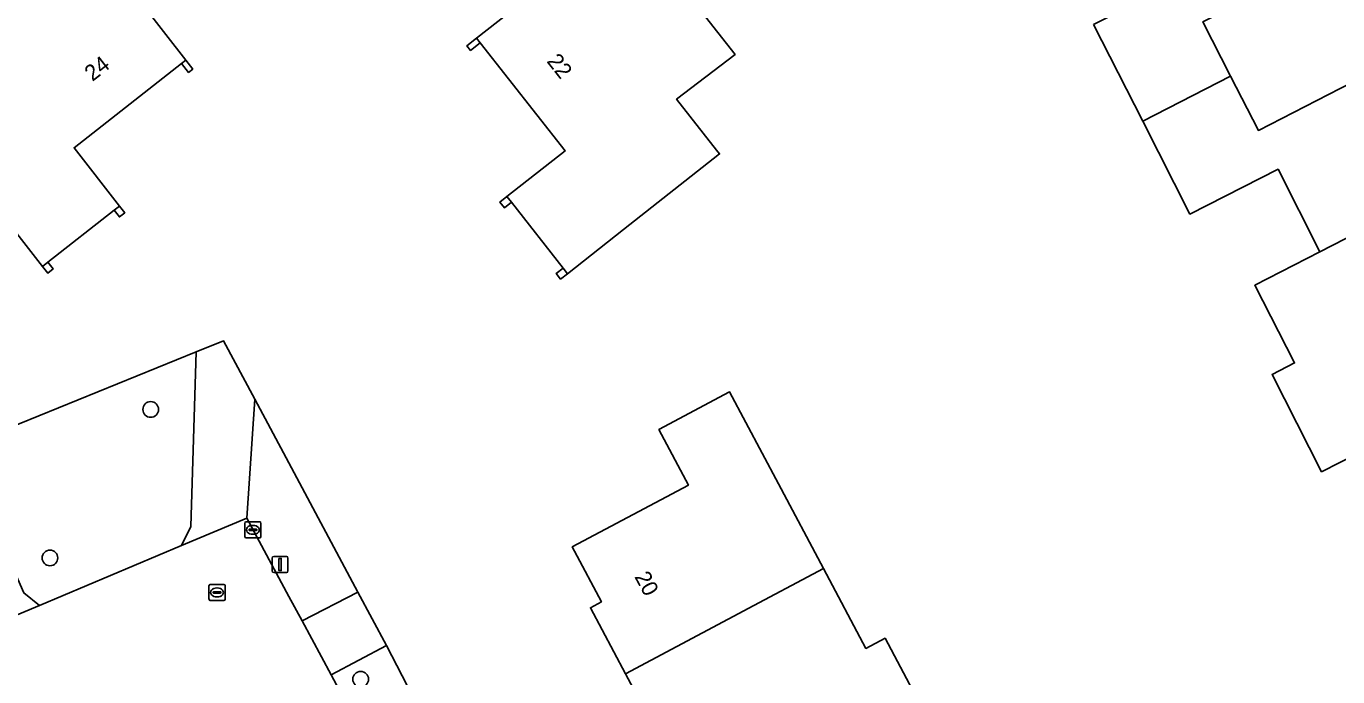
# Model space of a CAD drawing. Extents: x 162417 to 163722, y 384268 to 385417.
# Drawn here: x 163483.6 to 163565.5, y 384925 to 384965.6 of the extents above; entities that cross this region are included whole.
import ezdxf

# ---------------------------------------------------------------- set-up
doc = ezdxf.new("R2010")
doc.units = 0
for name, color, linetype in [('IMGEO_Boom', 7, 'Continuous'), ('IMGEO_Erf', 7, 'Continuous'), ('IMGEO_Groenvoorziening', 7, 'Continuous'), ('IMGEO_Kolk', 7, 'Continuous'), ('IMGEO_Lichtmast', 7, 'Continuous'), ('IMGEO_Muur', 7, 'Continuous'), ('IMGEO_Pand', 7, 'Continuous'), ('IMGEO_Pand_nummerreeks', 7, 'Continuous'), ('IMGEO_Rijbaan_lokaal_gesloten', 7, 'Continuous'), ('IMGEO_Rioolput', 7, 'Continuous'), ('IMGEO_Voetpad_open', 7, 'Continuous')]:
    doc.layers.add(name, color=color, linetype=linetype)

msp = doc.modelspace()

# ---------------------------------------------------------------- linework, layer by layer
at = {"layer": 'IMGEO_Boom'}
for centre in [(163491.37, 384941.649), (163485.084, 384932.387), (163504.475, 384924.82)]:
    msp.add_circle(centre, 0.489, dxfattribs=at)
at = {"layer": 'IMGEO_Erf'}
msp.add_lwpolyline([(163517.384, 384950.12), (163516.948, 384949.777), (163516.672, 384950.127), (163517.108, 384950.471), (163513.88, 384954.573), (163513.444, 384954.23), (163513.166, 384954.583), (163513.602, 384954.926), (163517.23, 384957.781), (163511.929, 384964.517), (163511.333, 384964.048), (163511.104, 384964.339), (163511.7, 384964.808), (163515.034, 384967.432), (163517.566, 384969.425), (163518.37, 384968.403), (163521.985, 384971.248), (163527.844, 384963.8), (163524.188, 384961.001), (163526.689, 384957.823), (163526.874, 384957.588), (163520.878, 384952.87)], close=True, dxfattribs=at)
for points in [[(163490.912, 384966.818), (163493.56, 384963.439), (163493.996, 384962.883), (163493.734, 384962.677), (163493.298, 384963.233), (163486.585, 384957.972), (163489.43, 384954.341), (163489.756, 384953.925), (163489.419, 384953.662), (163489.094, 384954.077), (163484.955, 384950.834), (163485.281, 384950.419), (163484.944, 384950.154), (163484.618, 384950.57), (163481.829, 384954.129), (163479.862, 384952.587), (163476.911, 384952.94), (163474.138, 384956.462), (163474.608, 384960.569), (163476.576, 384960.345), (163476.793, 384960.516), (163477.154, 384960.055), (163480.497, 384962.675), (163480.747, 384965.663)], [(163566.719, 384938.915), (163564.445, 384937.758), (163561.353, 384943.836), (163562.758, 384944.551), (163560.274, 384949.399), (163564.346, 384951.484), (163561.728, 384956.63), (163556.229, 384953.832), (163553.281, 384959.628), (163550.211, 384965.663)], [(163557.032, 384965.826), (163558.766, 384962.44), (163560.499, 384959.055), (163567.785, 384962.786)], [(163479.466, 384939.261), (163494.207, 384945.241), (163495.918, 384945.927), (163497.872, 384942.291), (163500, 384938.325), (163504.307, 384930.256), (163506.079, 384926.915), (163514.598, 384910.454), (163515.734, 384908.25), (163515.928, 384908.35), (163518.056, 384909.494), (163552.107, 384845.87), (163579.211, 384794.807)], [(163523.203, 384921.016), (163521.007, 384925.15), (163518.811, 384929.284), (163519.5, 384929.65), (163517.818, 384932.817), (163517.68, 384933.078), (163524.927, 384936.928), (163523.084, 384940.398), (163527.5, 384942.745), (163530.551, 384937.002), (163533.357, 384931.72), (163536.002, 384926.739), (163537.203, 384927.376), (163540.273, 384921.598)]]:
    msp.add_lwpolyline(points, dxfattribs=at)
at = {"layer": 'IMGEO_Groenvoorziening'}
for points in [[(163493.3, 384933.155), (163493.875, 384934.348), (163494.207, 384945.241), (163479.466, 384939.261), (163483.455, 384930.207), (163484.425, 384929.423)], [(163500, 384938.325), (163497.872, 384942.291), (163497.361, 384934.859), (163500, 384929.981), (163500.82, 384928.465), (163504.307, 384930.256)], [(163506.079, 384926.915), (163502.633, 384925.084), (163503.817, 384922.872), (163505.981, 384923.979), (163513.523, 384909.9), (163514.598, 384910.454)]]:
    msp.add_lwpolyline(points, close=True, dxfattribs=at)
at = {"layer": 'IMGEO_Kolk'}
for p, q in [((163497.248, 384933.714), (163497.248, 384934.566)), ((163497.323, 384934.64), (163498.175, 384934.64)), ((163497.736, 384934.42), (163497.761, 384934.42)), ((163498.249, 384934.566), (163498.249, 384933.714)), ((163498.175, 384933.64), (163497.323, 384933.64)), ((163497.507, 384934.134), (163497.507, 384934.146)), ((163497.945, 384934.097), (163497.547, 384934.097)), ((163497.55, 384934.183), (163497.948, 384934.183)), ((163497.759, 384933.86), (163497.734, 384933.86)), ((163497.991, 384934.146), (163497.991, 384934.134))]:
    msp.add_line(p, q, dxfattribs=at)
for points in [[(163497.248, 384933.714), (163497.248, 384934.566)], [(163497.323, 384934.64), (163498.175, 384934.64)], [(163498.249, 384934.566), (163498.249, 384933.714)], [(163498.175, 384933.64), (163497.323, 384933.64)]]:
    msp.add_lwpolyline(points, dxfattribs=at)
for centre, radius, start, end in [((163497.325, 384934.564), 0.0765, 91.55205, 178.44795), ((163497.325, 384934.564), 0.0765, 91.55205, 178.44795), ((163498.173, 384934.564), 0.0765, 1.55205, 88.44795), ((163498.173, 384934.564), 0.0765, 1.55205, 88.44795), ((163497.325, 384933.716), 0.0765, 181.55205, 268.44795), ((163497.325, 384933.716), 0.0765, 181.55205, 268.44795), ((163497.547, 384934.143), 0.0403, 85.87752, 175.75265), ((163497.544, 384934.133), 0.0366, 178.93798, 274.71019), ((163497.948, 384934.14), 0.043, 264.86636, 352.45326), ((163497.952, 384934.145), 0.0386, 1.73085, 96.63898), ((163498.173, 384933.716), 0.0765, 271.55205, 358.44795), ((163498.173, 384933.716), 0.0765, 271.55205, 358.44795)]:
    msp.add_arc(centre, radius, start, end, dxfattribs=at)
for centre, major_axis, ratio, start_param, end_param in [((163497.735, 384934.14), (-0.387, 0.002), 0.722429, 4.712389, 7.853982), ((163497.76, 384934.14), (-0.39, 0.002), 0.717154, 1.570796, 4.712389)]:
    msp.add_ellipse(centre, major_axis=major_axis, ratio=ratio, start_param=start_param, end_param=end_param, dxfattribs=at)
at = {"layer": 'IMGEO_Lichtmast'}
for p, q in [((163498.949, 384931.577), (163498.949, 384932.377)), ((163498.949, 384932.377), (163498.949, 384931.577)), ((163499.049, 384932.477), (163499.839, 384932.477)), ((163499.839, 384932.477), (163499.049, 384932.477)), ((163499.939, 384932.377), (163499.939, 384931.577)), ((163499.939, 384931.577), (163499.939, 384932.377)), ((163499.839, 384931.477), (163499.049, 384931.477)), ((163499.049, 384931.477), (163499.839, 384931.477))]:
    msp.add_line(p, q, dxfattribs=at)
msp.add_lwpolyline([(163499.369, 384932.352), (163499.519, 384932.352), (163499.519, 384931.602), (163499.369, 384931.602), (163499.369, 384932.352)], dxfattribs=at)
for centre, start, end in [((163499.049, 384932.377), 90, 180), ((163499.049, 384932.377), 90, 180), ((163499.839, 384932.377), 0, 90), ((163499.839, 384932.377), 360, 90), ((163499.049, 384931.577), 180, 270), ((163499.049, 384931.577), 180, 270), ((163499.839, 384931.577), 270, 0), ((163499.839, 384931.577), 270, 0)]:
    msp.add_arc(centre, 0.1, start, end, dxfattribs=at)
at = {"layer": 'IMGEO_Muur'}
for points in [[(163511.929, 384964.517), (163511.7, 384964.808), (163511.104, 384964.339), (163511.333, 384964.048)], [(163493.56, 384963.439), (163493.298, 384963.233), (163493.734, 384962.677), (163493.996, 384962.883)], [(163513.602, 384954.926), (163513.166, 384954.583), (163513.444, 384954.23), (163513.88, 384954.573)], [(163489.756, 384953.925), (163489.43, 384954.341), (163489.094, 384954.077), (163489.419, 384953.662)], [(163484.955, 384950.834), (163484.618, 384950.57), (163484.944, 384950.154), (163485.281, 384950.419)], [(163517.108, 384950.471), (163516.672, 384950.127), (163516.948, 384949.777), (163517.384, 384950.12)]]:
    msp.add_lwpolyline(points, close=True, dxfattribs=at)
at = {"layer": 'IMGEO_Pand'}
for points in [[(163550.211, 384965.663), (163553.281, 384959.628), (163558.766, 384962.44), (163557.032, 384965.826), (163564.327, 384969.562), (163564.17, 384969.868), (163562.49, 384973.148), (163563.242, 384973.533), (163561.148, 384977.622), (163549.382, 384971.771), (163552.021, 384966.584)], [(163524.188, 384961.001), (163527.844, 384963.8), (163521.985, 384971.248), (163518.37, 384968.403), (163517.566, 384969.425), (163515.034, 384967.432), (163511.7, 384964.808), (163511.929, 384964.517), (163517.23, 384957.781), (163513.602, 384954.926), (163513.88, 384954.573), (163517.108, 384950.471), (163517.384, 384950.12), (163520.878, 384952.87), (163526.874, 384957.588), (163526.689, 384957.823)], [(163476.911, 384952.94), (163479.862, 384952.587), (163481.829, 384954.129), (163484.618, 384950.57), (163484.955, 384950.834), (163489.094, 384954.077), (163489.43, 384954.341), (163486.585, 384957.972), (163493.298, 384963.233), (163493.56, 384963.439), (163490.912, 384966.818), (163488.949, 384969.324), (163486.84, 384967.671), (163485.497, 384969.386), (163481.736, 384966.438), (163480.747, 384965.663), (163480.497, 384962.675), (163477.154, 384960.055), (163476.793, 384960.516), (163476.576, 384960.345), (163474.608, 384960.569), (163474.138, 384956.462)], [(163553.281, 384959.628), (163556.229, 384953.832), (163561.728, 384956.63), (163564.346, 384951.484), (163572.333, 384955.575), (163570.232, 384959.678), (163569.554, 384959.331), (163567.914, 384962.534), (163567.785, 384962.786), (163560.499, 384959.055), (163558.766, 384962.44)], [(163561.353, 384943.836), (163564.445, 384937.758), (163566.719, 384938.915), (163566.822, 384938.713), (163570.017, 384940.348), (163569.886, 384940.604), (163568.2, 384943.896), (163573.613, 384946.667), (163575.47, 384947.618), (163575.298, 384947.953), (163573.691, 384951.09), (163574.435, 384951.47), (163572.333, 384955.575), (163564.346, 384951.484), (163560.274, 384949.399), (163562.758, 384944.551)], [(163527.5, 384942.745), (163523.084, 384940.398), (163524.927, 384936.928), (163517.68, 384933.078), (163517.818, 384932.817), (163519.5, 384929.65), (163518.811, 384929.284), (163521.007, 384925.15), (163529.011, 384929.411), (163532.695, 384931.368), (163533.357, 384931.72), (163530.551, 384937.002)], [(163537.203, 384927.376), (163536.002, 384926.739), (163533.357, 384931.72), (163532.695, 384931.368), (163529.011, 384929.411), (163521.007, 384925.15), (163523.203, 384921.016), (163523.973, 384921.425), (163525.67, 384918.229), (163525.807, 384917.971), (163527.599, 384918.924), (163533.076, 384921.834), (163534.758, 384918.668), (163537.142, 384919.935), (163540.273, 384921.598)]]:
    msp.add_lwpolyline(points, close=True, dxfattribs=at)
at = {"layer": 'IMGEO_Rijbaan_lokaal_gesloten'}
msp.add_lwpolyline([(163496.246, 384922.739), (163497.491, 384920.419), (163503.817, 384922.872), (163502.633, 384925.084), (163500.82, 384928.465), (163500, 384929.981), (163497.361, 384934.859), (163493.3, 384933.155), (163484.425, 384929.423), (163480.987, 384927.976), (163480.777, 384927.888), (163459.676, 384919.014), (163456.078, 384917.501), (163455.799, 384917.384), (163407.071, 384896.895)], dxfattribs=at)
at = {"layer": 'IMGEO_Rioolput'}
for p, q in [((163495.009, 384929.806), (163495.009, 384930.658)), ((163495.084, 384930.732), (163495.936, 384930.732)), ((163495.268, 384930.226), (163495.268, 384930.238)), ((163495.311, 384930.275), (163495.709, 384930.275)), ((163495.497, 384930.512), (163495.522, 384930.512)), ((163495.752, 384930.238), (163495.752, 384930.226)), ((163496.01, 384930.658), (163496.01, 384929.806)), ((163495.936, 384929.732), (163495.084, 384929.732)), ((163495.706, 384930.189), (163495.308, 384930.189)), ((163495.52, 384929.952), (163495.495, 384929.952))]:
    msp.add_line(p, q, dxfattribs=at)
for points in [[(163495.009, 384929.806), (163495.009, 384930.658)], [(163495.084, 384930.732), (163495.936, 384930.732)], [(163496.01, 384930.658), (163496.01, 384929.806)], [(163495.936, 384929.732), (163495.084, 384929.732)]]:
    msp.add_lwpolyline(points, dxfattribs=at)
for centre, radius, start, end in [((163495.086, 384930.656), 0.0765, 91.55205, 178.44795), ((163495.086, 384930.656), 0.0765, 91.55205, 178.44795), ((163495.308, 384930.235), 0.0403, 85.87752, 175.75265), ((163495.305, 384930.225), 0.0366, 178.93798, 274.71019), ((163495.709, 384930.232), 0.043, 264.86636, 352.45326), ((163495.713, 384930.237), 0.0386, 1.73085, 96.63898), ((163495.934, 384930.656), 0.0765, 1.55205, 88.44795), ((163495.934, 384930.656), 0.0765, 1.55205, 88.44795), ((163495.086, 384929.808), 0.0765, 181.55205, 268.44795), ((163495.086, 384929.808), 0.0765, 181.55205, 268.44795), ((163495.934, 384929.808), 0.0765, 271.55205, 358.44795), ((163495.934, 384929.808), 0.0765, 271.55205, 358.44795)]:
    msp.add_arc(centre, radius, start, end, dxfattribs=at)
for centre, major_axis, ratio, start_param, end_param in [((163495.496, 384930.232), (-0.387, 0.002), 0.722429, 4.712389, 7.853982), ((163495.521, 384930.232), (-0.39, 0.002), 0.717154, 1.570796, 4.712389)]:
    msp.add_ellipse(centre, major_axis=major_axis, ratio=ratio, start_param=start_param, end_param=end_param, dxfattribs=at)
at = {"layer": 'IMGEO_Voetpad_open'}
for points in [[(163493.3, 384933.155), (163497.361, 384934.859), (163497.872, 384942.291), (163495.918, 384945.927), (163494.207, 384945.241), (163493.875, 384934.348)], [(163479.466, 384939.261), (163477.129, 384938.273), (163476.005, 384937.8), (163478.195, 384934.989), (163480.791, 384929.164), (163480.777, 384927.888), (163480.987, 384927.976), (163484.425, 384929.423), (163483.455, 384930.207)], [(163500.82, 384928.465), (163502.633, 384925.084), (163506.079, 384926.915), (163504.307, 384930.256)]]:
    msp.add_lwpolyline(points, close=True, dxfattribs=at)

# ---------------------------------------------------------------- texts
at = {"layer": 'IMGEO_Pand_nummerreeks'}
for s, rotation, p in [('22', 308.19889, (163516.047, 384963.359)), ('24', 38.0845, (163487.737, 384962.076)), ('20', 298.28099, (163521.54, 384931.22))]:
    msp.add_text(s, height=1, rotation=rotation, dxfattribs=at).set_placement(p)

doc.saveas('drawing.dxf')
